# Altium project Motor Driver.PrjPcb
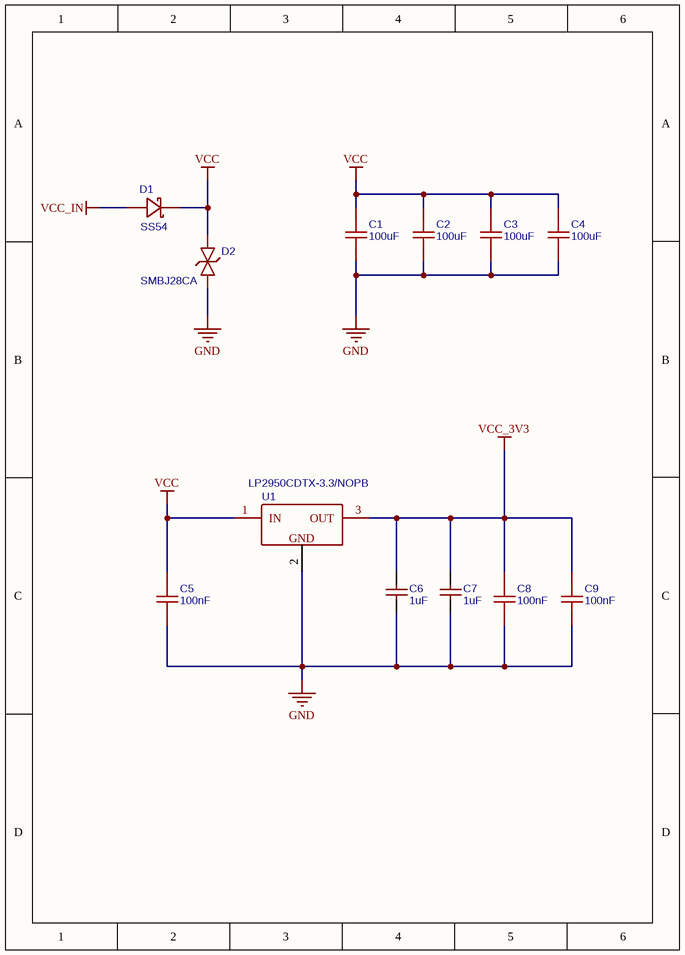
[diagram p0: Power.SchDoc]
5 sheets, 43 parts. Net scope: global (net labels, ports and power ports of the same name join across sheets).
Board file: Motor Driver.PcbDoc
Sheets:
  Power.SchDoc
  Drive.SchDoc
  MCU.SchDoc
  Port.SchDoc
  Interface.SchDoc

## Sheet Power.SchDoc
size 127 x 177 mm; SheetNumber: 1; SheetTotal: 5

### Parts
C1  100uF  [C1206]
C2  100uF  [C1206]
C3  100uF  [C1206]
C4  100uF  [C1206]
C5  100nF  [C0603]
C6  1uF  [C0603]
C7  1uF  [C0603]
C8  100nF  [C0603]
C9  100nF  [C0603]
D1  SS54  [SMA_L4.3-W2.6-LS5.0-RD]
D2  SMBJ28CA  [SMB_L4.6-W3.6-LS5.3-BI]
U1  LP2950CDTX-3.3/NOPB  [TO-252-2_L6.6-W6.1-P4.57-LS9.9-BR-CW]

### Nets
GND: C1.2 C2.2 C3.2 C4.2 C5.1 C6.1 C7.1 C8.1 C9.1 D2.1 U1.2(GND)
VCC: C1.1 C2.1 C3.1 C4.1 C5.2 D1.1 D2.2 U1.1(IN)
VCC_3V3: C6.2 C7.2 C8.2 C9.2 U1.3(OUT)
VCC_IN: D1.2

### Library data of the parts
C1-C4 = 100uF: BOM_Manufacturer: Murata Electronics; BOM_Manufacturer Part: GRM31CR61A107ME05L; nameAlias: Capacitance; Contributor: LCSC
C5 C8 C9 = 100nF: BOM_Manufacturer: SAMSUNG; BOM_Manufacturer Part: CL10B104KB8NNNC; nameAlias: Capacitance
C6 C7 = 1uF: BOM_Manufacturer Part: CL10A105KB8NNNC; BOM_Manufacturer: SAMSUNG; nameAlias: Capacitance
D1 = SS54_C727065: BOM_Manufacturer: TWGMC; Contributor: LCSC
D2 = SMBJ28CA_C908204: BOM_Manufacturer: FUXINSEMI; Contributor: LCSC
U1 = LP2950CDTX-3.3/NOPB: BOM_Manufacturer: TI; Contributor: LCSC

## Sheet Drive.SchDoc
size 203 x 101 mm; SheetNumber: 2; SheetTotal: 5
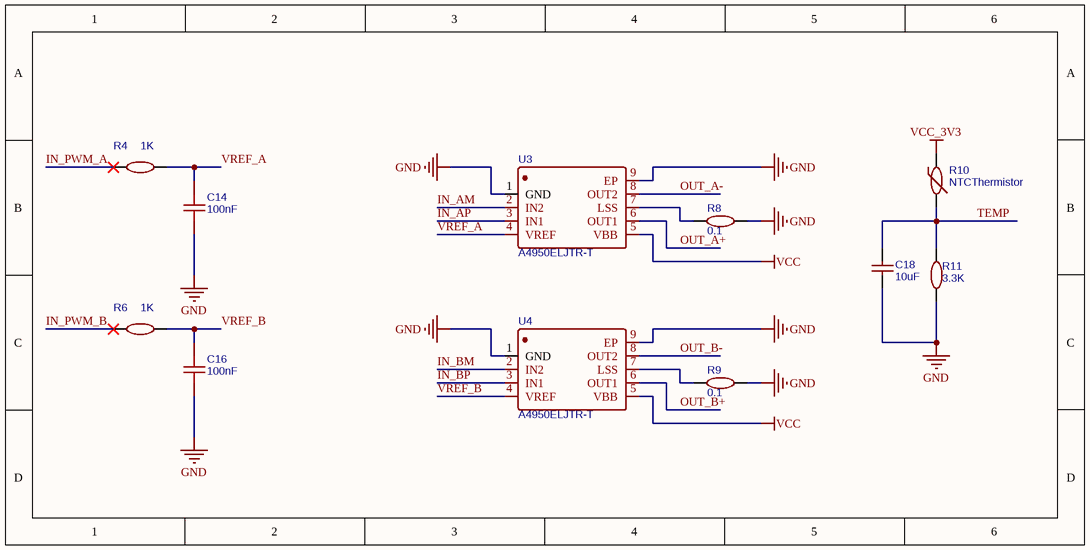
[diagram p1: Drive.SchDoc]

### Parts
C14  100nF  [C0603]
C16  100nF  [C0603]
C18  10uF  [C1206]
R4  1K  [R0603]
R6  1K  [R0603]
R8  0.1  [R1206]
R9  0.1  [R1206]
R10  NTCThermistor  [R0402]
R11  3.3K  [R0603_NEW]
U3  A4950ELJTR-T  [SOIC-8_L4.9-W3.9-P1.27-LS6.0-BL-EP]
U4  A4950ELJTR-T  [SOIC-8_L4.9-W3.9-P1.27-LS6.0-BL-EP]

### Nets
GND: C14.1 C16.1 C18.1 R8.2 R9.2 R11.1 U3.1(GND) U3.9(EP) U4.1(GND) U4.9(EP)
VCC: U3.5(VBB) U4.5(VBB)
VCC_3V3: R10.1
IN_AM: U3.2(IN2)
IN_AP: U3.3(IN1)
IN_BM: U4.2(IN2)
IN_BP: U4.3(IN1)
IN_PWM_A: R4.1
IN_PWM_B: R6.1
OUT_A+: U3.6(OUT1)
OUT_A-: U3.8(OUT2)
OUT_B+: U4.6(OUT1)
OUT_B-: U4.8(OUT2)
TEMP: C18.2 R10.2 R11.2
VREF_A: C14.2 R4.2 U3.4(VREF)
VREF_B: C16.2 R6.2 U4.4(VREF)
NetR8_1: R8.1 U3.7(LSS)
NetR9_1: R9.1 U4.7(LSS)

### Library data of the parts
C14 C16 = 100nF: as C5 on sheet Power
C18 = 10uF: BOM_Manufacturer Part: CL31A106KBHNNNE; BOM_Manufacturer: SAMSUNG; nameAlias: Capacitance
R4 R6 = 1K: BOM_Manufacturer: UniOhm; BOM_Manufacturer Part: 0603WAF1001T5E; nameAlias: Resistance (Ohms)
R8 R9 = 0.1: BOM_Manufacturer: UniOhm; BOM_Manufacturer Part: 1206W4F100LT5E; nameAlias: Resistance (Ohms)
R10 = NTCThermistor: BOM_Manufacturer: MuRata; BOM_Manufacturer Part: NCP15XH103F03RC; nameAlias: Value
R11 = 3.3K: BOM_Manufacturer: UniOhm; BOM_Manufacturer Part: 0603WAF3301T5E; nameAlias: Resistance (Ohms)
U3 U4 = A4950ELJTR-T: BOM_Manufacturer: ALLEGRO

## Sheet MCU.SchDoc
size 228 x 127 mm; SheetNumber: 3; SheetTotal: 5
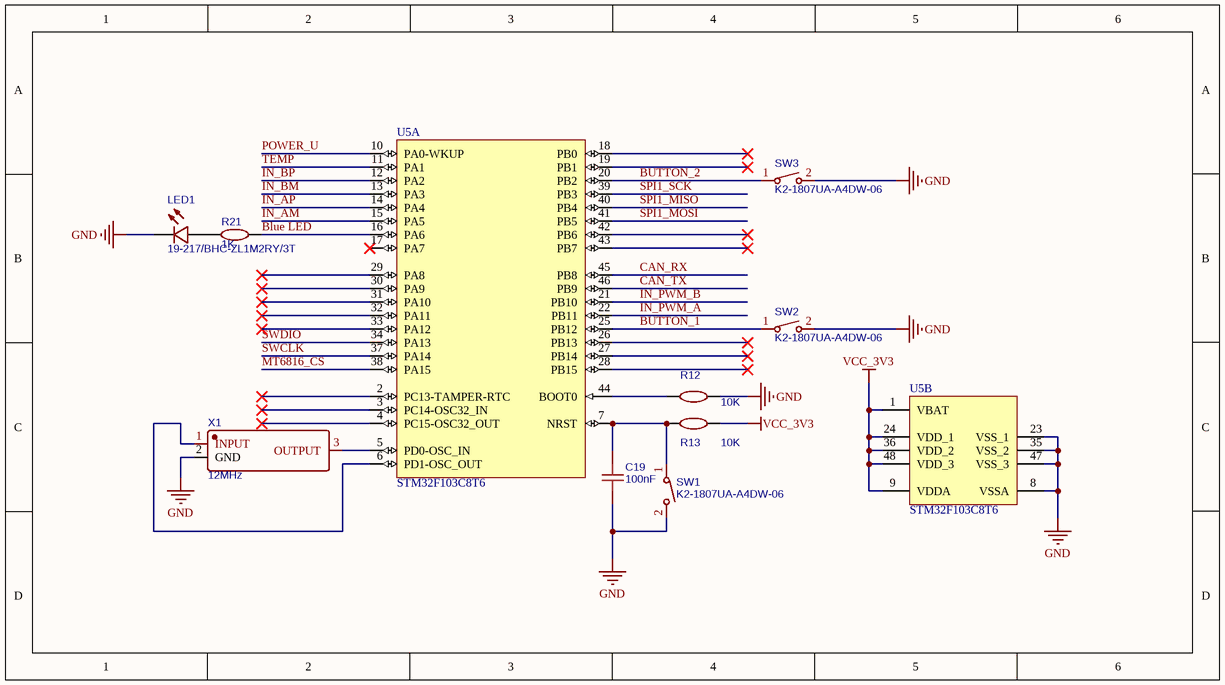
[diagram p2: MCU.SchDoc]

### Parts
C19  100nF  [C0603]
LED1  19-217/BHC-ZL1M2RY/3T  [LED0603-R-RD_BLUE]
R12  10K  [R0603]
R13  10K  [R0603]
R21  1K  [R0603]
SW1  K2-1807UA-A4DW-06  [KEY-SMD_L4.0-W2.9-L]
SW2  K2-1807UA-A4DW-06  [KEY-SMD_L4.0-W2.9-L]
SW3  K2-1807UA-A4DW-06  [KEY-SMD_L4.0-W2.9-L]
U5  STM32F103C8T6  [STM-LQFP48_L]  (parts A,B of 2)
X1  12MHz  [CRYSTAL-SMD_3P-L3.2-W1.3-P1.2-BL]

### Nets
GND: C19.1 LED1.2(C) R12.2 SW1.2 SW2.2 SW3.2 U5.8(VSSA) U5.23(VSS_1) U5.35(VSS_2) U5.47(VSS_3) X1.2(GND)
VCC_3V3: R13.2 U5.1(VBAT) U5.9(VDDA) U5.24(VDD_1) U5.36(VDD_2) U5.48(VDD_3)
Blue LED: R21.2 U5.16(PA6)
BUTTON_1: SW2.1 U5.25(PB12)
BUTTON_2: SW3.1 U5.20(PB2)
CAN_RX: U5.45(PB8)
CAN_TX: U5.46(PB9)
IN_AM: U5.15(PA5)
IN_AP: U5.14(PA4)
IN_BM: U5.13(PA3)
IN_BP: U5.12(PA2)
IN_PWM_A: U5.22(PB11)
IN_PWM_B: U5.21(PB10)
MT6816_CS: U5.38(PA15)
POWER_U: U5.10(PA0-WKUP)
SPI1_MISO: U5.40(PB4)
SPI1_MOSI: U5.41(PB5)
SPI1_SCK: U5.39(PB3)
SWCLK: U5.37(PA14)
SWDIO: U5.34(PA13)
TEMP: U5.11(PA1)
NetC19_2: C19.2 R13.1 SW1.1 U5.7(NRST)
NetLED1_1: LED1.1(A) R21.1
NetR12_1: R12.1 U5.44(BOOT0)
NetU5_5: U5.5(PD0-OSC_IN) X1.3(OUTPUT)
NetU5_6: U5.6(PD1-OSC_OUT) X1.1(INPUT)

Not connected (* = marked no-connect by the designer): U5 2(PC13-TAMPER-RTC)* 3(PC14-OSC32_IN)* 4(PC15-OSC32_OUT)* 17(PA7)* 18(PB0)* 19(PB1)* 26(PB13)* 27(PB14)* 28(PB15)* 29(PA8)* 30(PA9)* 31(PA10)* 32(PA11)* 33(PA12)* 42(PB6)* 43(PB7)*

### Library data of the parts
C19 = 100nF: as C5 on sheet Power
LED1 = 19-217/BHC-ZL1M2RY/3T: BOM_Manufacturer: EVERLIGHT
R12 R13 = 10K: BOM_Manufacturer: UniOhm; BOM_Manufacturer Part: 0603WAF1002T5E; nameAlias: Resistance (Ohms)
R21 = 1K: as R4 on sheet Drive
SW1-SW3 = K2-1807UA-A4DW-06: BOM_Manufacturer: Korean Hroparts Elec; Contributor: LCSC
U5 = CMP-0237-00215-3: ARM Cortex-M3 32-bit MCU, 64 KB Flash, 20 KB Internal RAM, 37 I/Os, 48-pin LQFP, -40 to 85 degC, Tray; Supply Voltage(Vcc) min (V): 2; Internal RAM Size (kB): 20; FLASH Size (Prog) (kB): 64; A/D Converter: 2x12-bit (10 Channel); I/Os (High Current): 37; Operating Frequency(F) (Processor speed) (MHz): 72
X1 = 12MHz: BOM_Manufacturer: muRata(村田); BOM_Manufacturer Part: CSTNE12M0G52A000R0; nameAlias: Frequency; Contributor: LCSC

## Sheet Port.SchDoc
size 127 x 177 mm; SheetNumber: 4; SheetTotal: 5
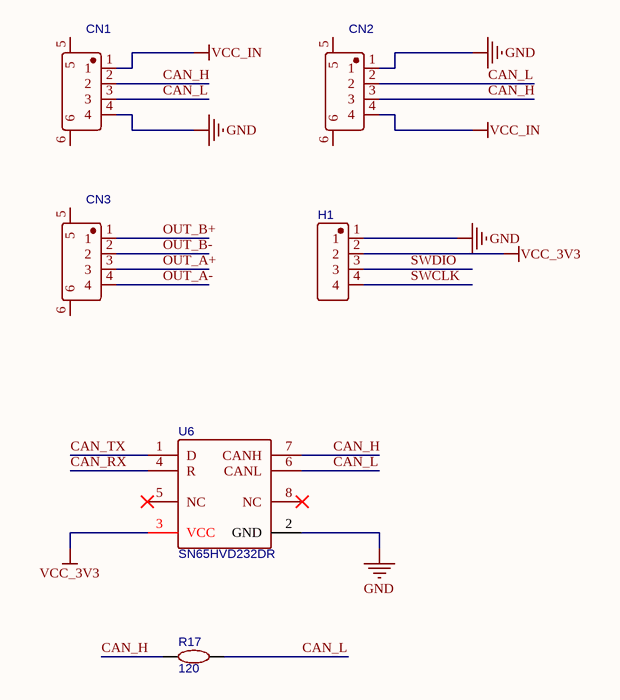
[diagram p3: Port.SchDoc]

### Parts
CN1  (no value)  [CONN-SMD_4P-P2.50-WAFER-254W-4P]
CN2  (no value)  [CONN-SMD_4P-P2.50-WAFER-254W-4P]
CN3  (no value)  [CONN-SMD_4P-P2.50-WAFER-254W-4P]
H1  (no value)  [HDR-TH_4P-P2.54-H-M-W10.4]
R17  120  [R0603]
U6  SN65HVD232DR  [SOIC-8_L5.0-W4.0-P1.27-LS6.0-BL]

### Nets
GND: CN1.4 CN2.1 H1.1 U6.2(GND)
VCC_3V3: H1.2 U6.3(VCC)
VCC_IN: CN1.1 CN2.4
CAN_H: CN1.2 CN2.3 R17.1 U6.7(CANH)
CAN_L: CN1.3 CN2.2 R17.2 U6.6(CANL)
CAN_RX: U6.4(R)
CAN_TX: U6.1(D)
OUT_A+: CN3.3
OUT_A-: CN3.4
OUT_B+: CN3.1
OUT_B-: CN3.2
SWCLK: H1.4
SWDIO: H1.3

Not connected (* = marked no-connect by the designer): CN1 5 6; CN2 5 6; CN3 5 6; U6 5(NC)* 8(NC)*

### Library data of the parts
CN1-CN3 = WAFER-254W-4P: BOM_Manufacturer: XUNPU(讯普); Contributor: LCSC
H1 = 2.54-1*4P反弯排针: BOM_Manufacturer: BOOMELE(博穆精密); Contributor: LCSC
R17 = 120: BOM_Manufacturer: UniOhm; BOM_Manufacturer Part: 0603WAF1200T5E; nameAlias: Resistance (Ohms)
U6 = SN65HVD232DR: BOM_Manufacturer: TI

## Sheet Interface.SchDoc
size 127 x 127 mm; SheetNumber: 5; SheetTotal: 5
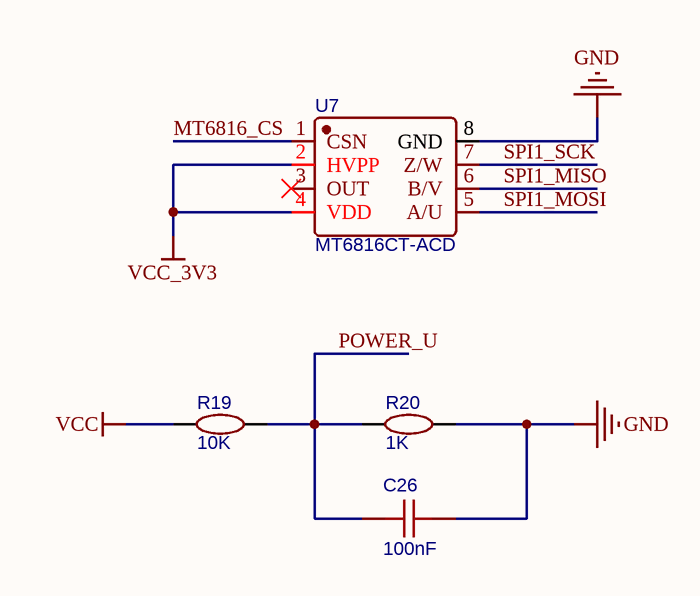
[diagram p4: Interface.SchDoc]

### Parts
C26  100nF  [C0603]
R19  10K  [R0603]
R20  1K  [R0603]
U7  MT6816CT-ACD  [SOP-8_L5.0-W4.0-P1.27-LS6.0-BL]

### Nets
GND: C26.2 R20.2 U7.8(GND)
VCC: R19.1
VCC_3V3: U7.2(HVPP) U7.4(VDD)
MT6816_CS: U7.1(CSN)
POWER_U: C26.1 R19.2 R20.1
SPI1_MISO: U7.6(B/V)
SPI1_MOSI: U7.5(A/U)
SPI1_SCK: U7.7(Z/W)

Not connected (* = marked no-connect by the designer): U7 3(OUT)*

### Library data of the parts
C26 = 100nF: as C5 on sheet Power
R19 = 10K: as R12 on sheet MCU
R20 = 1K: as R4 on sheet Drive
U7 = MT6816CT-ACD: BOM_Manufacturer: Magn Tek; Contributor: LCSC

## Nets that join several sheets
GND: Power (11 pins), Drive (10 pins), MCU (11 pins), Port (CN1.4 CN2.1 H1.1 U6.2), Interface (C26.2 R20.2 U7.8)
VCC: Power (8 pins), Drive (U3.5 U4.5), Interface (R19.1)
VCC_3V3: Power (5 pins), Drive (R10.1), MCU (6 pins), Port (H1.2 U6.3), Interface (U7.2 U7.4)
VCC_IN: Power (D1.2), Port (CN1.1 CN2.4)
CAN_RX: MCU (U5.45), Port (U6.4)
CAN_TX: MCU (U5.46), Port (U6.1)
IN_AM: Drive (U3.2), MCU (U5.15)
IN_AP: Drive (U3.3), MCU (U5.14)
IN_BM: Drive (U4.2), MCU (U5.13)
IN_BP: Drive (U4.3), MCU (U5.12)
IN_PWM_A: Drive (R4.1), MCU (U5.22)
IN_PWM_B: Drive (R6.1), MCU (U5.21)
MT6816_CS: MCU (U5.38), Interface (U7.1)
OUT_A+: Drive (U3.6), Port (CN3.3)
OUT_A-: Drive (U3.8), Port (CN3.4)
OUT_B+: Drive (U4.6), Port (CN3.1)
OUT_B-: Drive (U4.8), Port (CN3.2)
POWER_U: MCU (U5.10), Interface (C26.1 R19.2 R20.1)
SPI1_MISO: MCU (U5.40), Interface (U7.6)
SPI1_MOSI: MCU (U5.41), Interface (U7.5)
SPI1_SCK: MCU (U5.39), Interface (U7.7)
SWCLK: MCU (U5.37), Port (H1.4)
SWDIO: MCU (U5.34), Port (H1.3)
TEMP: Drive (C18.2 R10.2 R11.2), MCU (U5.11)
